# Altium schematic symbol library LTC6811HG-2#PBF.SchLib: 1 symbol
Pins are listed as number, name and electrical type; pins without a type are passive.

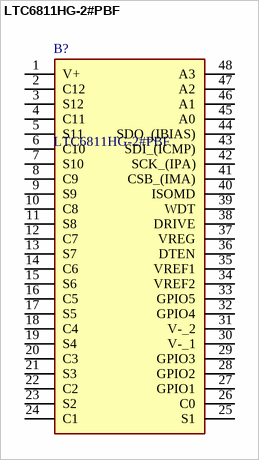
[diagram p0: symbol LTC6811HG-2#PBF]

## LTC6811HG-2#PBF
designator B?
Multicell Battery Balancer Automotive 48-Pin SSOP Tube; Manufacturer_Name: Analog Devices; Geometry.Height: 2mm
footprint SOP50P780X200-48N
pins: 1 V+, 2 C12, 3 S12, 4 C11, 5 S11, 6 C10, 7 S10, 8 C9, 9 S9, 10 C8, 11 S8, 12 C7, 13 S7, 14 C6, 15 S6, 16 C5, 17 S5, 18 C4, 19 S4, 20 C3, 21 S3, 22 C2, 23 S2, 24 C1, 25 S1, 26 C0, 27 GPIO1, 28 GPIO2, 29 GPIO3, 30 V-_1, 31 V-_2, 32 GPIO4, 33 GPIO5, 34 VREF2, 35 VREF1, 36 DTEN, 37 VREG, 38 DRIVE, 39 WDT, 40 ISOMD, 41 CSB_(IMA), 42 SCK_(IPA), 43 SDI_(ICMP), 44 SDO_(IBIAS), 45 A0, 46 A1, 47 A2, 48 A3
